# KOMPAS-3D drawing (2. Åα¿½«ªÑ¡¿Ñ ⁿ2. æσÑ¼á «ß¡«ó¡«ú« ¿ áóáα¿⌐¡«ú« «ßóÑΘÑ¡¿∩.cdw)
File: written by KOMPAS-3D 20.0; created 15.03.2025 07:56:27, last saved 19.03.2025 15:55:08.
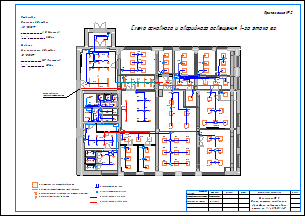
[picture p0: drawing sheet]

Sheet 1: A3, landscape

Document properties: Автор: User; Полное имя файла: \\Storage\20 Отдел\Мои документы\Крашенинников Е\ТЗ 1й этаж юг\Схема основного и аварийного освещения.cdw

Title block, sheet 1: scale: 1:1; Количество листов документа: 1; Форматы листов документа: A3

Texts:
  GOST Common
  Приложение №2
  Составил
  Фамилия
  Подпись
  Дата
  Наименование планировки
  Ведущий инженер энергетик
  Крашенинников
  Приложение № 3
  Схема монтажа основного и
  аварийного освещения 1-го
  этажа юг, в/о 27-31/А-Г
  Начальник 20 отдела
  Меренков
  Утверждаю
  АО "НИИЭТ"
  Зам. начальника 20 отдела
  ШСР
  - светильник LED 36Вт 595х595х34мм
  - светодиодный светильник LINER/P40-L40
  - накладная панель Led-GL-24 для потолка Грильято
  - панель светодиодная IN 12 Вт
  Схема основного и аварийного освещения 1-го этажа юг.
  рк1
  рк4
  рк3
  рк2
  гр1
  гр2
  ркА6
  - выключатели 1кл., 2кл.
  - расределительная коробка
  - кабель ВВГнг (А) LS 3х1,5
  ркА5
  ВВГ нг (А)FRLS 3х1,5
  от РК на лестничном марше
  ркА1
  ркА2
  ркА3
  рк5
  ркА4
  - кабель ВВГнг (А) FRLS 3х1,5
  Аварийная
  Стили документа
  FP_1_ISO 0
  FP_1_ISO 1
  FP_1_ISO 2
  FP_1_ISO 3
  FP_1_ISO 4
  FP_1_ISO 5
  FP_1_ISO 6
  FP_1_ISO 7
  FP_1_ISO 8
  FP_1_ISO 9
  FP_1_ISO 10
  FP_1_ISO 11
  FP_1_ISO 12
  FP_1_ISO 13
  FP_1_ISO 14
  FP_1_ISO 15
  FP_2_ISO 0
  FP_2_ISO 1
  FP_2_ISO 2
  FP_2_ISO 3
  FP_2_ISO 4
  FP_2_ISO 5
  FP_2_ISO 6
  FP_2_ISO 7
  FP_2_ISO 8
  FP_2_ISO 9
  FP_2_ISO 10
  FP_2_ISO 11
  FP_2_ISO 12
  FP_2_ISO 13
  FP_2_ISO 14
  FP_2_ISO 15
  FP_3_ISO 0
  FP_3_ISO 1
  FP_3_ISO 2
  FP_3_ISO 3
  FP_3_ISO 4
  FP_3_ISO 5
  FP_3_ISO 6
  FP_3_ISO 7
  FP_3_ISO 8
  FP_3_ISO 9
  FP_3_ISO 10
  FP_3_ISO 11
  FP_3_ISO 12
  FP_3_ISO 13
  FP_3_ISO 14
  FP_3_ISO 15
  FP_4_ISO 0
  FP_4_ISO 1
  FP_4_ISO 2
  FP_4_ISO 3
  FP_4_ISO 4
  FP_4_ISO 5
  FP_4_ISO 6
  FP_4_ISO 7
  FP_4_ISO 8
  FP_4_ISO 9
  FP_4_ISO 10
  FP_4_ISO 11
  FP_4_ISO 12
  FP_4_ISO 13
  FP_4_ISO 14
  FP_4_ISO 15
  FP_5_ISO 0
  FP_5_ISO 1
  FP_5_ISO 2
  FP_5_ISO 3
  FP_5_ISO 4
  FP_5_ISO 5
  FP_5_ISO 6
  FP_5_ISO 7
  FP_5_ISO 8
  FP_5_ISO 9
  FP_5_ISO 10
  FP_5_ISO 11
  FP_5_ISO 12
  FP_5_ISO 13
  FP_5_ISO 14
  FP_5_ISO 15
  FP_6_ISO 0
  FP_6_ISO 1
  FP_6_ISO 2
  FP_6_ISO 3
  FP_6_ISO 4
  FP_6_ISO 5
  FP_6_ISO 6
  FP_6_ISO 7
  FP_6_ISO 8
  FP_6_ISO 9
  FP_6_ISO 10
  FP_6_ISO 11
  FP_6_ISO 12
  FP_6_ISO 13
  FP_6_ISO 14
  FP_6_ISO 15
  FP_7_ISO 0
  FP_7_ISO 1
  FP_7_ISO 2
  FP_7_ISO 3
  FP_7_ISO 4
  FP_7_ISO 5
  FP_7_ISO 6
  FP_7_ISO 7
  FP_7_ISO 8
  FP_7_ISO 9
  FP_7_ISO 10
  FP_7_ISO 11
  FP_7_ISO 12
  FP_7_ISO 13
  FP_7_ISO 14
  FP_7_ISO 15
  FP_8_ISO 0
  FP_8_ISO 1
  FP_8_ISO 2
  FP_8_ISO 3
  FP_8_ISO 4
  FP_8_ISO 5
  FP_8_ISO 6
  FP_8_ISO 7
  FP_8_ISO 8
  FP_8_ISO 9
  FP_8_ISO 10
  FP_8_ISO 11
  FP_8_ISO 12
  FP_8_ISO 13
  FP_8_ISO 14
  FP_8_ISO 15
  FP_9_ISO 0
  FP_9_ISO 1
  FP_9_ISO 2
  FP_9_ISO 3
  FP_9_ISO 4
  FP_9_ISO 5
  FP_9_ISO 6
  FP_9_ISO 7
  FP_9_ISO 8
  FP_9_ISO 9
  FP_9_ISO 10
  FP_9_ISO 11
  FP_9_ISO 12
  FP_9_ISO 13
  FP_9_ISO 14
  FP_9_ISO 15
  FP_10_ISO 0
  FP_10_ISO 1
  FP_10_ISO 2
  FP_10_ISO 3
  FP_10_ISO 4
  FP_10_ISO 5
  FP_10_ISO 6
  FP_10_ISO 7
  FP_10_ISO 8
  FP_10_ISO 9
  FP_10_ISO 10
  FP_10_ISO 11
  FP_10_ISO 12
  FP_10_ISO 13
  FP_10_ISO 14
  FP_10_ISO 15
  FP_11_ISO 0
  FP_11_ISO 1
  FP_11_ISO 2
  FP_11_ISO 3
  FP_11_ISO 4
  FP_11_ISO 5
  FP_11_ISO 6
  FP_11_ISO 7
  FP_11_ISO 8
  FP_11_ISO 9
  FP_11_ISO 10
  FP_11_ISO 11
  FP_11_ISO 12
  FP_11_ISO 13
  FP_11_ISO 14
  FP_11_ISO 15
  FP_12_ISO 0
  FP_12_ISO 1
  FP_12_ISO 2
  FP_12_ISO 3
  FP_12_ISO 4
  FP_12_ISO 5
  FP_12_ISO 6
  FP_12_ISO 7
  FP_12_ISO 8
  FP_12_ISO 9
  FP_12_ISO 10
  FP_12_ISO 11
  FP_12_ISO 12
  FP_12_ISO 13
  FP_12_ISO 14
  FP_12_ISO 15
  FP_13_ISO 0
  FP_13_ISO 1
  FP_13_ISO 2
  FP_13_ISO 3
  FP_13_ISO 4
  FP_13_ISO 5
  FP_13_ISO 6
  FP_13_ISO 7
  FP_13_ISO 8
  FP_13_ISO 9
  FP_13_ISO 10
  FP_13_ISO 11
  FP_13_ISO 12
  FP_13_ISO 13
  FP_13_ISO 14
  FP_13_ISO 15
  FP_14_ISO 0
  FP_14_ISO 1
  FP_14_ISO 2
  FP_14_ISO 3
  FP_14_ISO 4
  FP_14_ISO 5
  FP_14_ISO 6
  FP_14_ISO 7
  FP_14_ISO 8
  FP_14_ISO 9
  FP_14_ISO 10
  FP_14_ISO 11
  FP_14_ISO 12
  FP_14_ISO 13
  FP_14_ISO 14
  FP_14_ISO 15
  FP_15_ISO 0
  FP_15_ISO 1
  FP_15_ISO 2
  FP_15_ISO 3
  FP_15_ISO 4
  FP_15_ISO 5
  FP_15_ISO 6
  FP_15_ISO 7
  FP_15_ISO 8
  FP_15_ISO 9
  FP_15_ISO 10
  FP_15_ISO 11
  FP_15_ISO 12
  FP_15_ISO 13
  FP_15_ISO 14
  FP_15_ISO 15
  FP_16_ISO 0
  FP_16_ISO 1
  FP_16_ISO 2
  FP_16_ISO 3
  FP_16_ISO 4
  FP_16_ISO 5
  FP_16_ISO 6
  FP_16_ISO 7
  FP_16_ISO 8
  FP_16_ISO 9
  FP_16_ISO 10
  FP_16_ISO 11
  FP_16_ISO 12
  FP_16_ISO 13
  FP_16_ISO 14
  FP_16_ISO 15
  FP_17_ISO 0
  FP_17_ISO 1
  FP_17_ISO 2
  FP_17_ISO 3
  FP_17_ISO 4
  FP_17_ISO 5
  FP_17_ISO 6
  FP_17_ISO 7
  FP_17_ISO 8
  FP_17_ISO 9
  FP_17_ISO 10
  FP_17_ISO 11
  FP_17_ISO 12
  FP_17_ISO 13
  FP_17_ISO 14
  FP_17_ISO 15
  FP_18_ISO 0
  FP_18_ISO 1
  FP_18_ISO 2
  FP_18_ISO 3
  FP_18_ISO 4
  FP_18_ISO 5
  FP_18_ISO 6
  FP_18_ISO 7
  FP_18_ISO 8
  FP_18_ISO 9
  FP_18_ISO 10
  FP_18_ISO 11
  FP_18_ISO 12
  FP_18_ISO 13
  FP_18_ISO 14
  FP_18_ISO 15
  FP_19_ISO 0
  FP_19_ISO 1
  FP_19_ISO 2
  FP_19_ISO 3
  FP_19_ISO 4
  FP_19_ISO 5
  FP_19_ISO 6
  FP_19_ISO 7
  FP_19_ISO 8
  FP_19_ISO 9
  FP_19_ISO 10
  FP_19_ISO 11
  FP_19_ISO 12
  FP_19_ISO 13
  FP_19_ISO 14
  FP_19_ISO 15
  FP_20_ISO 0
  FP_20_ISO 1
  FP_20_ISO 2
  FP_20_ISO 3
  FP_20_ISO 4
  FP_20_ISO 5
  FP_20_ISO 6
  FP_20_ISO 7
  FP_20_ISO 8
  FP_20_ISO 9
  FP_20_ISO 10
  FP_20_ISO 11
  FP_20_ISO 12
  FP_20_ISO 13
  FP_20_ISO 14
  FP_20_ISO 15
  FP_21_ISO 0
  FP_21_ISO 1
  FP_21_ISO 2
  FP_21_ISO 3
  FP_21_ISO 4
  FP_21_ISO 5
  FP_21_ISO 6
  FP_21_ISO 7
  FP_21_ISO 8
  FP_21_ISO 9
  FP_21_ISO 10
  FP_21_ISO 11
  FP_21_ISO 12
  FP_21_ISO 13
  FP_21_ISO 14
  FP_21_ISO 15
  FP_22_ISO 0
  FP_22_ISO 1
  FP_22_ISO 2
  FP_22_ISO 3
  FP_22_ISO 4
  FP_22_ISO 5
  FP_22_ISO 6
  FP_22_ISO 7
  FP_22_ISO 8
  FP_22_ISO 9
  FP_22_ISO 10
  FP_22_ISO 11
  FP_22_ISO 12
  FP_22_ISO 13
  FP_22_ISO 14
  FP_22_ISO 15
  FP_23_ISO 0
  FP_23_ISO 1
  FP_23_ISO 2
  FP_23_ISO 3
  FP_23_ISO 4
  FP_23_ISO 5
  FP_23_ISO 6
  FP_23_ISO 7
  FP_23_ISO 8
  FP_23_ISO 9
  FP_23_ISO 10
  FP_23_ISO 11
  FP_23_ISO 12
  FP_23_ISO 13
  FP_23_ISO 14
  FP_23_ISO 15
  FP_24_ISO 0
  FP_24_ISO 1
  FP_24_ISO 2
  FP_24_ISO 3
  FP_24_ISO 4
  FP_24_ISO 5
  FP_24_ISO 6
  FP_24_ISO 7
  FP_24_ISO 8
  FP_24_ISO 9
  FP_24_ISO 10
  FP_24_ISO 11
  FP_24_ISO 12
  FP_24_ISO 13
  FP_24_ISO 14
  FP_24_ISO 15
  FP_25_ISO 0
  FP_25_ISO 1
  FP_25_ISO 2
  FP_25_ISO 3
  FP_25_ISO 4
  FP_25_ISO 5
  FP_25_ISO 6
  FP_25_ISO 7
  FP_25_ISO 8
  FP_25_ISO 9
  FP_25_ISO 10
  FP_25_ISO 11
  FP_25_ISO 12
  FP_25_ISO 13
  FP_25_ISO 14
  FP_25_ISO 15
  FP_26_ISO 0
  FP_26_ISO 1
  FP_26_ISO 2
  FP_26_ISO 3
  FP_26_ISO 4
  FP_26_ISO 5
  FP_26_ISO 6
  FP_26_ISO 7
  FP_26_ISO 8
  FP_26_ISO 9
  FP_26_ISO 10
  FP_26_ISO 11
  FP_26_ISO 12
  FP_26_ISO 13
  FP_26_ISO 14
  FP_26_ISO 15
  FP_27_ISO 0
  FP_27_ISO 1
  FP_27_ISO 2
  FP_27_ISO 3
  FP_27_ISO 4
  FP_27_ISO 5
  FP_27_ISO 6
  FP_27_ISO 7
  FP_27_ISO 8
  FP_27_ISO 9
  FP_27_ISO 10
  FP_27_ISO 11
  FP_27_ISO 12
  FP_27_ISO 13
  FP_27_ISO 14
  FP_27_ISO 15
  FP_28_ISO 0
  FP_28_ISO 1
  FP_28_ISO 2
  FP_28_ISO 3
  FP_28_ISO 4
  FP_28_ISO 5
  FP_28_ISO 6
  FP_28_ISO 7
  FP_28_ISO 8
  FP_28_ISO 9
  FP_28_ISO 10
  FP_28_ISO 11
  FP_28_ISO 12
  FP_28_ISO 13
  FP_28_ISO 14
  FP_28_ISO 15
  FP_29_ISO 0
  FP_29_ISO 1
  FP_29_ISO 2
  FP_29_ISO 3
  FP_29_ISO 4
  FP_29_ISO 5
  FP_29_ISO 6
  FP_29_ISO 7
  FP_29_ISO 8
  FP_29_ISO 9
  FP_29_ISO 10
  FP_29_ISO 11
  FP_29_ISO 12
  FP_29_ISO 13
  FP_29_ISO 14
  FP_29_ISO 15
  FP_30_ISO 0
  FP_30_ISO 1
  FP_30_ISO 2
  FP_30_ISO 3
  FP_30_ISO 4
  FP_30_ISO 5
  FP_30_ISO 6
  FP_30_ISO 7
  FP_30_ISO 8
  FP_30_ISO 9
  FP_30_ISO 10
  FP_30_ISO 11
  FP_30_ISO 12
  FP_30_ISO 13
  FP_30_ISO 14
  FP_30_ISO 15
  FP_31_ISO 0
  FP_31_ISO 1
  FP_31_ISO 2
  FP_31_ISO 3
  FP_31_ISO 4
  FP_31_ISO 5
  FP_31_ISO 6
  FP_31_ISO 7
  FP_31_ISO 8
  FP_31_ISO 9
  FP_31_ISO 10
  FP_31_ISO 11
  FP_31_ISO 12
  FP_31_ISO 13
  FP_31_ISO 14
  FP_31_ISO 15
  FP_32_ISO 0
  FP_32_ISO 1
  FP_32_ISO 2
  FP_32_ISO 3
  FP_32_ISO 4
  FP_32_ISO 5
  FP_32_ISO 6
  FP_32_ISO 7
  FP_32_ISO 8
  FP_32_ISO 9
  FP_32_ISO 10
  FP_32_ISO 11
  FP_32_ISO 12
  FP_32_ISO 13
  FP_32_ISO 14
  FP_32_ISO 15
  FP_33_ISO 0
  FP_33_ISO 1
  FP_33_ISO 2
  FP_33_ISO 3
  FP_33_ISO 4
  FP_33_ISO 5
  FP_33_ISO 6
  FP_33_ISO 7
  FP_33_ISO 8
  FP_33_ISO 9
  FP_33_ISO 10
  FP_33_ISO 11
  FP_33_ISO 12
  FP_33_ISO 13
  FP_33_ISO 14
  FP_33_ISO 15
  FP_34_ISO 0
  FP_34_ISO 1
  FP_34_ISO 2
  FP_34_ISO 3
  FP_34_ISO 4
  FP_34_ISO 5
  FP_34_ISO 6
  FP_34_ISO 7
  FP_34_ISO 8
  FP_34_ISO 9
  FP_34_ISO 10
  FP_34_ISO 11
  FP_34_ISO 12
  FP_34_ISO 13
  FP_34_ISO 14
  FP_34_ISO 15
  FP_35_ISO 0
  FP_35_ISO 1
  FP_35_ISO 2
  FP_35_ISO 3
  FP_35_ISO 4
  FP_35_ISO 5
  FP_35_ISO 6
  FP_35_ISO 7
  FP_35_ISO 8
  FP_35_ISO 9
  FP_35_ISO 10
  FP_35_ISO 11
  FP_35_ISO 12
  FP_35_ISO 13
  FP_35_ISO 14
  FP_35_ISO 15
  FP_36_ISO 0
  FP_36_ISO 1
  FP_36_ISO 2
  FP_36_ISO 3
  FP_36_ISO 4
  FP_36_ISO 5
  FP_36_ISO 6
  FP_36_ISO 7
  FP_36_ISO 8
  FP_36_ISO 9
  FP_36_ISO 10
  FP_36_ISO 11
  FP_36_ISO 12
  FP_36_ISO 13
  FP_36_ISO 14
  FP_36_ISO 15
  FP_37_ISO 0
  FP_37_ISO 1
  FP_37_ISO 2
  FP_37_ISO 3
  FP_37_ISO 4
  FP_37_ISO 5
  FP_37_ISO 6
  FP_37_ISO 7
  FP_37_ISO 8
  FP_37_ISO 9
  FP_37_ISO 10
  FP_37_ISO 11
  FP_37_ISO 12
  FP_37_ISO 13
  FP_37_ISO 14
  FP_37_ISO 15
  FP_38_ISO 0
  FP_38_ISO 1
  FP_38_ISO 2
  FP_38_ISO 3
  FP_38_ISO 4
  FP_38_ISO 5
  FP_38_ISO 6
  FP_38_ISO 7
  FP_38_ISO 8
  FP_38_ISO 9
  FP_38_ISO 10
  FP_38_ISO 11
  FP_38_ISO 12
  FP_38_ISO 13
  FP_38_ISO 14
  FP_38_ISO 15
  FP_39_ISO 0
  FP_39_ISO 1
  FP_39_ISO 2
  FP_39_ISO 3
  FP_39_ISO 4
  FP_39_ISO 5
  FP_39_ISO 6
  FP_39_ISO 7
  FP_39_ISO 8
  FP_39_ISO 9
  FP_39_ISO 10
  FP_39_ISO 11
  FP_39_ISO 12
  FP_39_ISO 13
  FP_39_ISO 14
  FP_39_ISO 15
  FP_40_ISO 0
  FP_40_ISO 1
  FP_40_ISO 2
  FP_40_ISO 3
  FP_40_ISO 4
  FP_40_ISO 5
  FP_40_ISO 6
  FP_40_ISO 7
  FP_40_ISO 8
  FP_40_ISO 9
  FP_40_ISO 10
  FP_40_ISO 11
  FP_40_ISO 12
  FP_40_ISO 13
  FP_40_ISO 14
  FP_40_ISO 15
  FP_41_ISO 0
  FP_41_ISO 1
  FP_41_ISO 2
  FP_41_ISO 3
  FP_41_ISO 4
  FP_41_ISO 5
  FP_41_ISO 6
  FP_41_ISO 7
  FP_41_ISO 8
  FP_41_ISO 9
  FP_41_ISO 10
  FP_41_ISO 11
  FP_41_ISO 12
  FP_41_ISO 13
  FP_41_ISO 14
  FP_41_ISO 15
  FP_42_ISO 0
  FP_42_ISO 1
  FP_42_ISO 2
  FP_42_ISO 3
  FP_42_ISO 4
  FP_42_ISO 5
  FP_42_ISO 6
  FP_42_ISO 7
  FP_42_ISO 8
  FP_42_ISO 9
  FP_42_ISO 10
  FP_42_ISO 11
  FP_42_ISO 12
  FP_42_ISO 13
  FP_42_ISO 14
  FP_42_ISO 15
  FP_43_ISO 0
  FP_43_ISO 1
  FP_43_ISO 2
  FP_43_ISO 3
  FP_43_ISO 4
  FP_43_ISO 5
  FP_43_ISO 6
  FP_43_ISO 7
  FP_43_ISO 8
  FP_43_ISO 9
  FP_43_ISO 10
  FP_43_ISO 11
  FP_43_ISO 12
  FP_43_ISO 13
  FP_43_ISO 14
  FP_43_ISO 15
  Без основной надписи.
Dimensions and other numbers on the sheet: 1:1; 1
